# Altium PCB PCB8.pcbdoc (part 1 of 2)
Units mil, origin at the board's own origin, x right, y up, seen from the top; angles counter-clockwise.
Board outline 4659.3 x 3372.91 mil, 4 copper layers (Top Layer, Inner1, Inner2, Bottom Layer); 143 components, 120 nets, 588 pads, 154 vias.
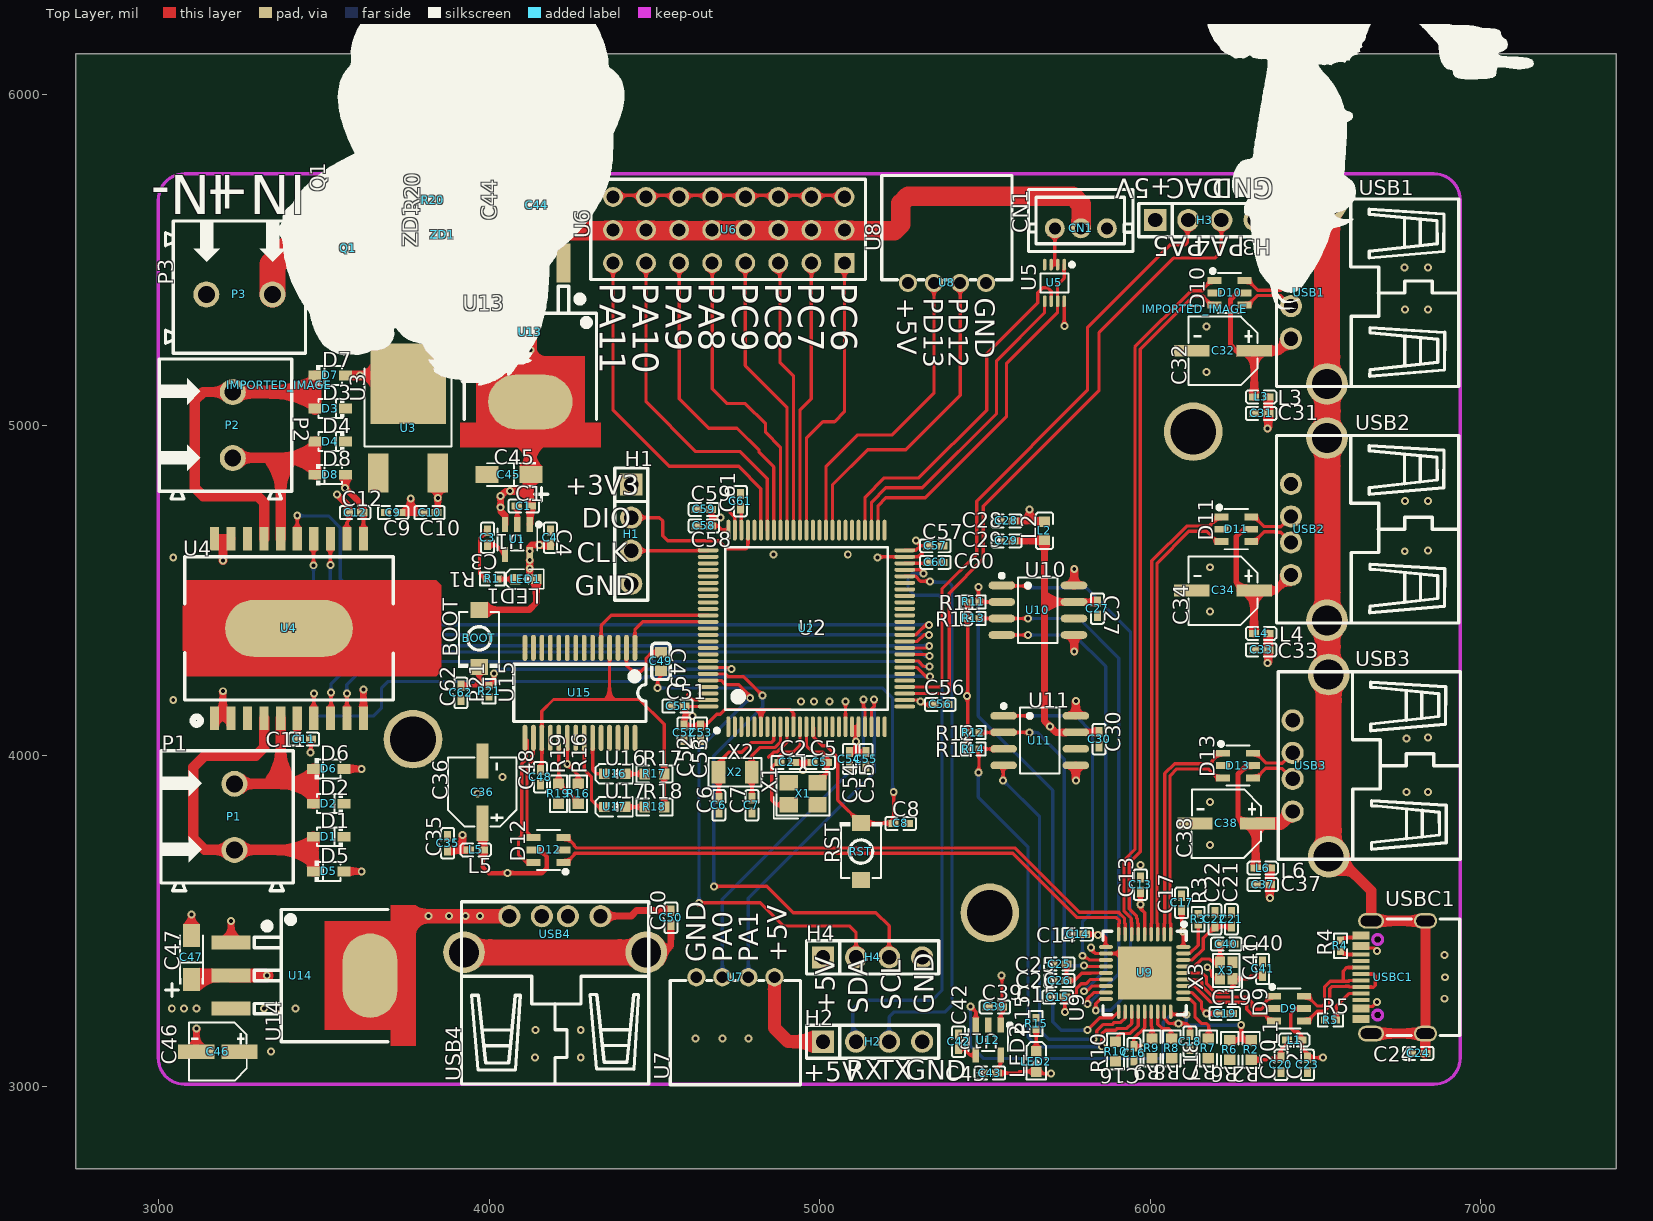
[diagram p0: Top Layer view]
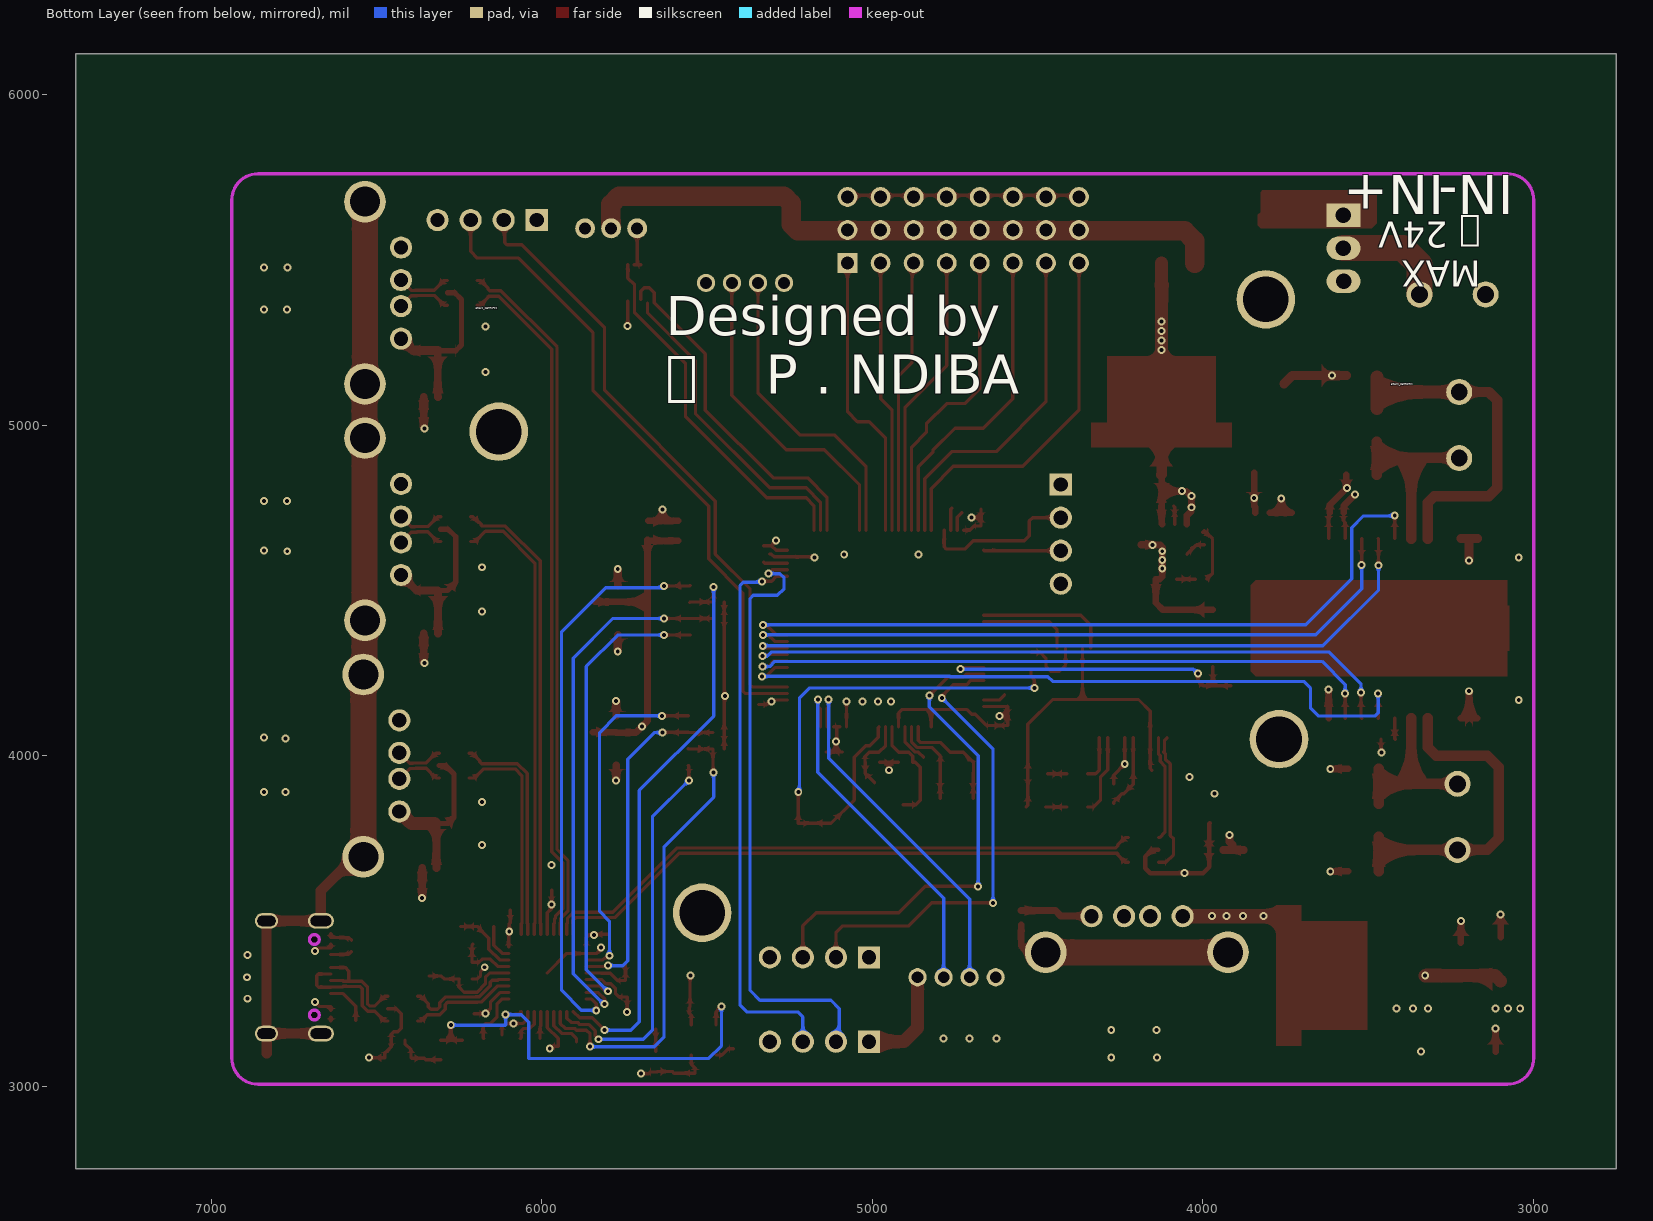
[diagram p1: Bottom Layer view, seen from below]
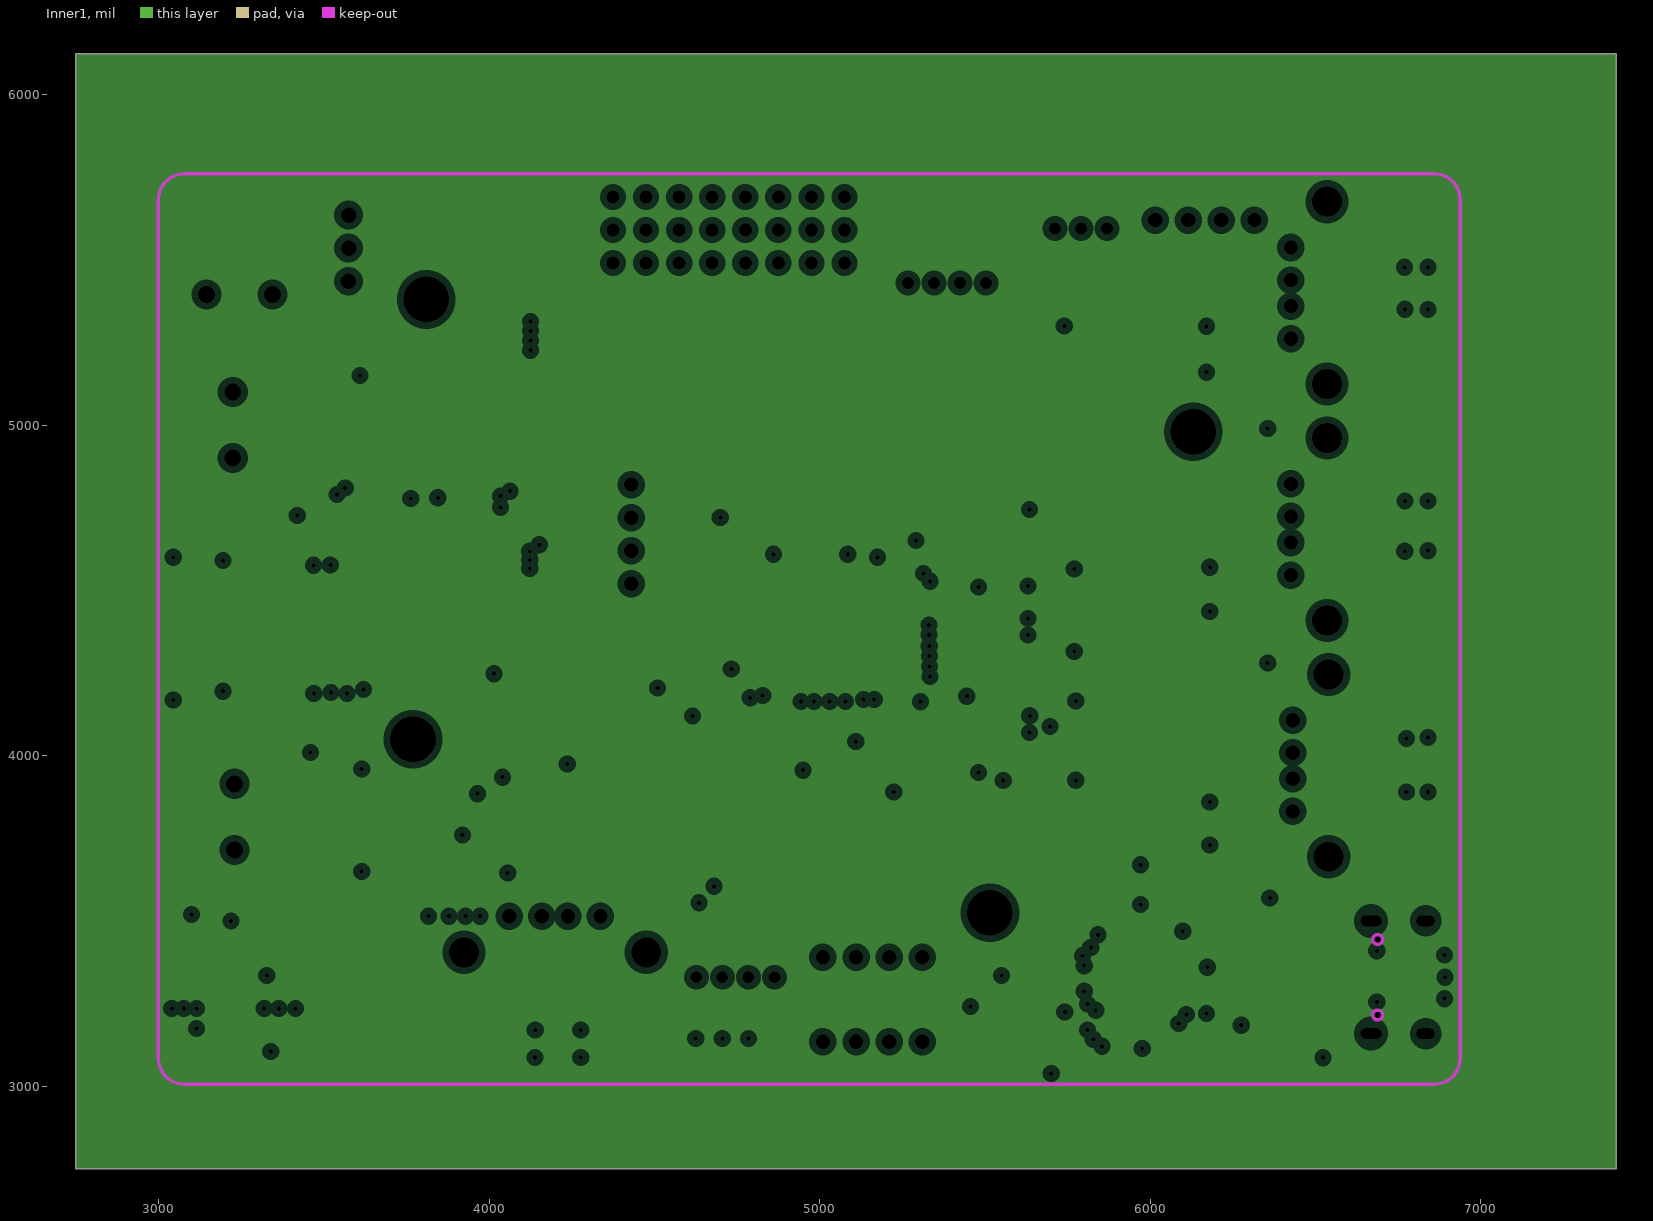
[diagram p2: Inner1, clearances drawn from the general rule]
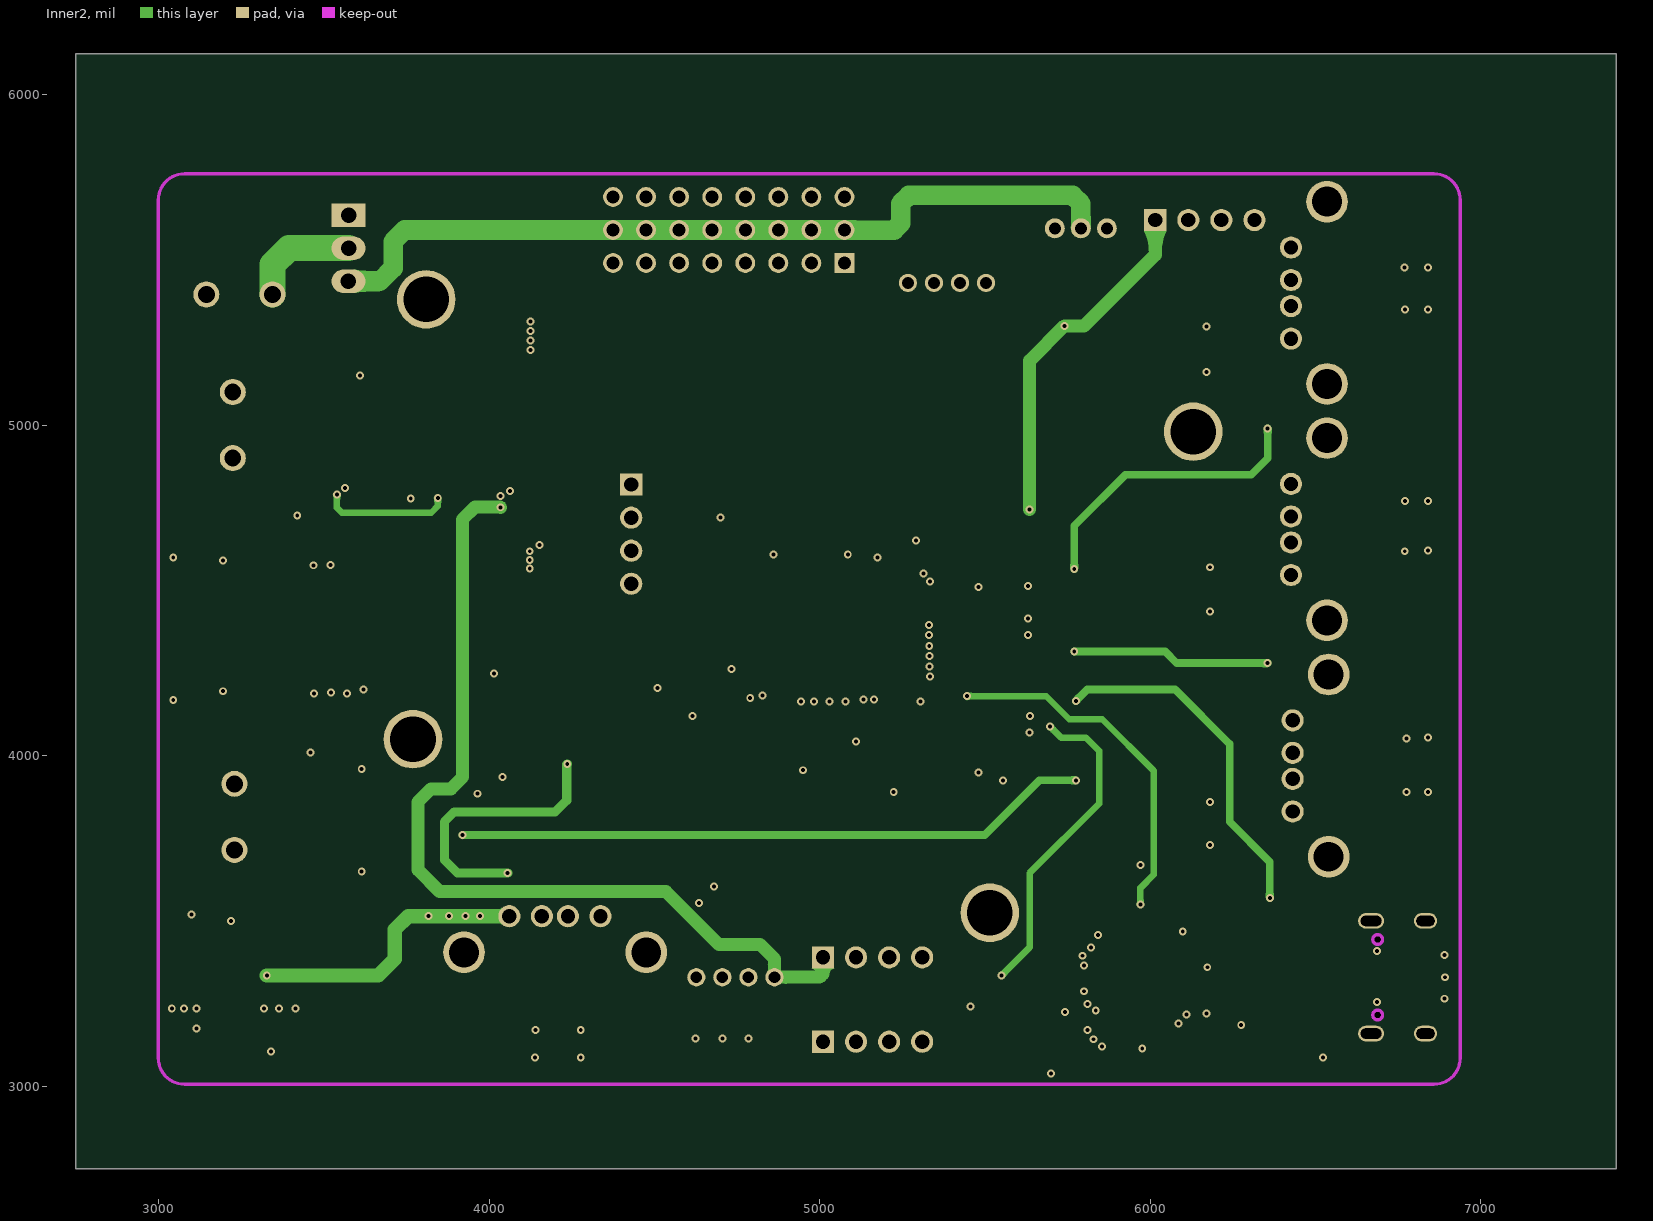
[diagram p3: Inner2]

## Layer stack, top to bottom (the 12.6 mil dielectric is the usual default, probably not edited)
Top Layer: signal copper (thickness not stored)
Dielectric: dielectric 12.6, FR-4, Dk 4.8
Inner1: plane copper (thickness not stored)
Dielectric: dielectric 12.6, FR-4, Dk 4.8
Inner2: signal copper (thickness not stored)
Dielectric: dielectric 12.6, FR-4, Dk 4.8
Bottom Layer: signal copper (thickness not stored)

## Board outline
7409.3,2750 2750,2750 2750,6122.91 7409.3,6122.91

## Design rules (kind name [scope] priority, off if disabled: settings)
BoardOutlineClearance copperThickness1oz [All] p0: genericclearance=10 ignorepadtopadclearanceinfootprint=FALSE except(0: Arc-SplitContinuation Track-SplitContinuation SMDPad-SplitContinuation THPad-SplitContinuation Via-SplitContinuation Fill-SplitContinuation Poly-SplitContinuation Region-SplitContinuation Text-SplitContinuation; 6: Track-CutoutEdge SMDPad-CutoutEdge THPad-CutoutEdge Via-CutoutEdge Region-CutoutEdge; 11.8: Track-OutlineEdge SMDPad-OutlineEdge THPad-OutlineEdge Via-OutlineEdge Fill-OutlineEdge Region-OutlineEdge Poly-OutlineEdge Text-OutlineEdge Fill-CutoutEdge)
BoardOutlineClearance copperThickness2oz [All] p0: genericclearance=10 ignorepadtopadclearanceinfootprint=FALSE except(0: Arc-SplitContinuation Track-SplitContinuation SMDPad-SplitContinuation THPad-SplitContinuation Via-SplitContinuation Fill-SplitContinuation Poly-SplitContinuation Region-SplitContinuation Text-SplitContinuation; 6: Track-CutoutEdge SMDPad-CutoutEdge THPad-CutoutEdge Via-CutoutEdge Region-CutoutEdge; 11.8: Track-OutlineEdge SMDPad-OutlineEdge THPad-OutlineEdge Via-OutlineEdge Fill-OutlineEdge Region-OutlineEdge Poly-OutlineEdge Text-OutlineEdge Fill-CutoutEdge)
Clearance copperThickness1oz [(InNet('OSC_IN') OR InNet('GND') OR InNet('OSC_OUT') OR InNet('OSC32_IN') OR InNet('NRST') OR InNet('+5V-D1') OR InNet('VCC') OR InNet('$4N1148') OR InNet('$3N2967') OR InNet('3V3_HUB') OR InNet('+5V_USB_FIL') OR InNet('AGND') OR InNet('$3N5997') OR InNet('$3N6212') OR InNet('XTALIN') OR InNet('XTALOUT') OR InNet('+5V_HOST_FIL') OR InNet('5V_HOST') OR InNet('$3N9069') OR InNet('+5V_USB_PORT2') OR InNet('$3N12252') OR InNet('+5V_USB_PORT3') OR InNet('$3N14705') OR InNet('+5V_USB_PORT4') OR InNet('+5V_USB_PORT1_FIL') OR InNet('+5V_USB_PORT1') OR InNet('+5V') OR InNet('$1N3755') OR InNet('+3V3') OR InNet('DUP_SERVO') OR InNet('OUT1') OR InNet('OUT2') OR InNet('OUT4') OR InNet('OUT3') OR InNet('USBDP_UP') OR InNet('USBDM_UP') OR InNet('C_DN') OR InNet('C_DP') OR InNet('USBDP_DN2') OR InNet('USBDM_DN2') OR InNet('$3N10765') OR InNet('$3N9020') OR InNet('USBDP_DN3') OR InNet('USBDM_DN3') OR InNet('$3N12261') OR InNet('$3N12248') OR InNet('USBDP_DN4') OR InNet('USBDM_DN4') OR InNet('$3N14709') OR InNet('$3N14704') OR InNet('USB1_DM') OR InNet('USB1_DP') OR InNet('VCCIO') OR InNet('$3N4638') OR InNet('$1N3758') OR InNet('$4N1145') OR InNet('$4N1153') OR InNet('$4N1154') OR InNet('$3N3794') OR InNet('$3N3790') OR InNet('$3N4557') OR InNet('$3N4535') OR InNet('$3N4529') OR InNet('$3N4524') OR InNet('VBUS_DET') OR InNet('$3N5818') OR InNet('USB_HUB_NOCS1') OR InNet('USB_HUB_NOCS2') OR InNet('PC9') OR InNet('PC8') OR InNet('PC7') OR InNet('PC6') OR InNet('ENC3_2') OR InNet('ENC3_1') OR InNet('ENB') OR InNet('ENA') OR InNet('ENC1_2') OR InNet('ENC1_1') OR InNet('OSC32_OUT') OR InNet('IN1') OR InNet('IN2') OR InNet('IN3') OR InNet('IN4') OR InNet('TX1') OR InNet('RX1') OR InNet('$4N1151') OR InNet('$4N1152') OR InNet('DUP_TX') OR InNet('DUP_RX') OR InNet('DUP_CTRL') OR InNet('USBDM_DN1') OR InNet('USBDP_DN1') OR InNet('USB_HUB_NOCS3') OR InNet('USB_HUB_PWR4') OR InNet('USB_HUB_NOCS4') OR InNet('USB_HUB_PWR3') OR InNet('USB_HUB_PWR2') OR InNet('USB_HUB_PWR1') OR InNet('$4N2277') OR InNet('+5V_PI') OR InNet('$4N3409') OR InNet('$4N3607') OR InNet('PA11') OR InNet('PA10') OR InNet('PA9') OR InNet('PA8') OR InNet('SWCLK') OR InNet('$1N6732') OR InNet('SWDIO') OR InNet('$1N6736') OR InNet('DEBUG_RX') OR InNet('DEBUG_TX') OR InNet('SDA') OR InNet('SCL') OR InNet('BOOT') OR InNet('MOSI') OR InNet('MISO') OR InNet('SCK') OR InNet('DAC2') OR InNet('DAC1'))] p1: gap=7 ignorepadtopadclearanceinfootprint=FALSE except(4: Track-Track; 6: Track-SMDPad SMDPad-SMDPad Track-THPad SMDPad-THPad THPad-THPad Track-Via SMDPad-Via THPad-Via Via-Via SMDPad-Fill THPad-Fill Via-Fill Fill-Fill Track-Region SMDPad-Region THPad-Region Via-Region Region-Region Track-Poly SMDPad-Poly THPad-Poly Via-Poly Fill-Poly Region-Poly Poly-Poly Track-Text SMDPad-Text THPad-Text Via-Text Fill-Text Region-Text Poly-Text Text-Text; 6.9: Track-Hole SMDPad-Hole THPad-Hole Via-Hole Fill-Hole Region-Hole Poly-Hole Text-Hole Sheet-Hole; 11.8: Track-Fill Fill-Region Track-Sheet SMDPad-Sheet THPad-Sheet Via-Sheet Fill-Sheet Region-Sheet Poly-Sheet Text-Sheet)
Clearance copperThickness2oz [All] p1: gap=7 ignorepadtopadclearanceinfootprint=FALSE except(6: Track-SMDPad SMDPad-SMDPad Track-THPad SMDPad-THPad THPad-THPad Track-Via SMDPad-Via THPad-Via Via-Via SMDPad-Fill THPad-Fill Via-Fill Fill-Fill Track-Region SMDPad-Region THPad-Region Via-Region Region-Region Track-Poly SMDPad-Poly THPad-Poly Via-Poly Fill-Poly Region-Poly Poly-Poly Track-Text SMDPad-Text THPad-Text Via-Text Fill-Text Region-Text Poly-Text Text-Text; 6.9: Track-Hole SMDPad-Hole THPad-Hole Via-Hole Fill-Hole Region-Hole Poly-Hole Text-Hole Sheet-Hole; 8: Track-Track; 11.8: Track-Fill Fill-Region Track-Sheet SMDPad-Sheet THPad-Sheet Via-Sheet Fill-Sheet Region-Sheet Poly-Sheet Text-Sheet)
DiffPairsRouting differentialPair [All] p1: maxuncoupledlength=10 minlimit=6 maxlimit=6 mostfreqgap=6 toplayer_minwidth=5 toplayer_prefwidth=10 toplayer_maxwidth=100 bottomlayer_minwidth=5 bottomlayer_prefwidth=10 bottomlayer_maxwidth=100 midlayer2_minwidth=5 midlayer2_prefwidth=10 midlayer2_maxwidth=100
PasteMaskExpansion pasteMaskExpansion [All] p1: expansion=0
PlaneConnect innerPlane [All] p1: planeconnectstyle=Relief reliefexpansion=20 reliefentries=4 reliefconductorwidth=10 reliefairgap=10
PolygonConnect copperRegion [All] p1: connectstyle=Relief reliefentries=4 reliefconductorwidth=10 polygonreliefangle="90 Angle" airgapwidth=10
RoutingVias viaSize [All] p1: viastyle="Through Hole" holewidth=12.0078 minholewidth=11.811 maxholewidth=248.0314 width=24.0158 minwidth=19.685 maxwidth=393.7008
SolderMaskExpansion solderMaskExpansion [All] p1: useseparateexpansions=TRUE expansion=2 expansionbottom=2
Width copperThickness1oz [All] p1: maxlimit=100 minlimit=5 preferedwidth=10
Width copperThickness2oz [All] p1: maxlimit=100 minlimit=8 preferedwidth=10

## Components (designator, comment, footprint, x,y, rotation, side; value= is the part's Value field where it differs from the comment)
BOOT "TS-1088-AR02016" SW-SMD_L3.9-W3.0-P4.45 3970,4354.8 r270 top
C1 "CL05A225MQ5NSNC" C0402 4105,4754.8 r180 top
C2 "TCC0402COG250K500AT" C0402 4900,3979.8 r180 top
C3 "CC0402KRX7R7BB104" C0402 3995.76,4659.01 r270 top
C4 "CL05A225MQ5NSNC" C0402 4185.76,4659.01 r270 top
C5 "TCC0402COG250K500AT" C0402 5000,3979.8 r0 top
C6 "TCC0402COG250K500AT" C0402 4695,3849.8 r90 top
C7 "TCC0402COG250K500AT" C0402 4795,3849.8 r90 top
C8 "CT41G-0402-2X1-16V-0.1μF-K(N)" C0402 5245,3794.8 r180 top
C9 "CL05A105KP5NNNC" C0402 3710,4734.8 r180 top
C10 "CT41G-0402-2X1-16V-0.1μF-K(N)" C0402 3820,4734.8 r0 top
C11 "GRM155R71C104KA88D" C0402 3440,4049.8 r180 top
C12 "GRM155R71C104KA88D" C0402 3595,4734.8 r180 top
C13 "CL05A225MQ5NSNC" C0402 5970,3609.8 r270 top
C14 "CC0402KRX7R7BB104" C0402 5780,3459.8 r180 top
C15 "CC0402KRX7R7BB104" C0402 5720,3269.8 r180 top
C16 "CC0402KRX7R7BB104" C0402 5950,3099.8 r270 top
C17 "CC0402KRX7R7BB104" C0402 6095,3554.8 r90 top
C18 "CC0402KRX7R7BB104" C0402 6120,3134.8 r270 top
C19 "CC0402KRX7R7BB104" C0402 6225,3219.8 r180 top
C20 "CL05A225MQ5NSNC" C0402 6395,3064.8 r90 top
C21 "CC0402KRX7R7BB104" C0402 6245,3504.8 r90 top
C22 "CC0402KRX7R9BB103" C0402 6195,3504.8 r90 top
C23 "CL05A225MQ5NSNC" C0402 6475,3064.8 r90 top
C24 "CC0402KRX7R9BB472" C0402 6810,3099.8 r180 top
C25 "CC0402KRX7R9BB103" C0402 5725,3369.8 r180 top
C26 "CC0402KRX7R7BB104" C0402 5725,3319.8 r180 top
C27 "CT41G-0402-2X1-16V-0.1μF-K(N)" C0402 5840,4444.8 r90 top
C28 "CL05A225KO5NQNC" C0402 5565,4709.8 r180 top
C29 "CL05A225KO5NQNC" C0402 5565,4649.8 r180 top
C30 "CT41G-0402-2X1-16V-0.1μF-K(N)" C0402 5845,4049.8 r90 top
C31 "CL05A225MQ5NSNC" C0402 6335,5034.8 r0 top
C32 "RVT1C101M0505" CAP-SMD_BD5.0-L5.3-W5.3-LS6.3-FD 6220,5224.8 r180 top
C33 "CL05A225MQ5NSNC" C0402 6335,4319.8 r0 top
C34 "RVT1C101M0505" CAP-SMD_BD5.0-L5.3-W5.3-LS6.3-FD 6220,4499.8 r180 top
C35 "CL05A225MQ5NSNC" C0402 3875,3734.8 r270 top
C36 "RVT1C101M0505" CAP-SMD_BD5.0-L5.3-W5.3-LS6.3-FD 3980,3889.8 r90 top
C37 "CL05A225MQ5NSNC" C0402 6340,3609.8 r0 top
C38 "RVT1C101M0505" CAP-SMD_BD5.0-L5.3-W5.3-LS6.3-FD 6230,3794.8 r180 top
C39 "CL05A225MQ5NSNC" C0402 5530,3239.8 r180 top
C40 "0402CG100J500NT" C0402 6230,3429.8 r0 top
C41 "0402CG100J500NT" C0402 6340,3354.8 r90 top
C42 "CC0402KRX7R7BB104" C0402 5420,3134.8 r270 top
C43 "CL05A225MQ5NSNC" C0402 5515,3039.8 r0 top
C44 "RST10UF16V013" CAP-SMD_BD4.0-L4.3-W4.3-FD 4145,5664.8 r0 top
C45 "TAJA106K016RNJ" CAP-SMD_L3.2-W1.6-RD-C7171 4060,4849.8 r180 top
C46 "RST10UF16V013" CAP-SMD_BD4.0-L4.3-W4.3-FD 3180,3104.8 r180 top
C47 "TAJA106K016RNJ" CAP-SMD_L3.2-W1.6-RD-C7171 3100,3389.8 r90 top
C48 "CC0402KRX7R7BB104" C0402 4155,3934.8 r90 top
C49 "CC0603KRX7R9BB104" C0603 4520,4284.8 r270 top
C50 "CC0402KRX7R9BB472" C0402 4550,3509.8 r270 top
C51 "GRM155R71A104KA01D" C0402 4570,4149.8 r180 top
C52 "GRM155R71A104KA01D" C0402 4590,4069.8 r270 top
C53 "GRM155R71A104KA01D" C0402 4640,4069.8 r270 top
C54 "GRM155R71A104KA01D" C0402 5090,3989.8 r270 top
C55 "GRM155R71A104KA01D" C0402 5140,3989.8 r270 top
C56 "GRM155R71A104KA01D" C0402 5365,4154.8 r0 top
C57 "GRM155R71A104KA01D" C0402 5350,4634.8 r0 top
C58 "GRM155R71A104KA01D" C0402 4650,4694.8 r180 top
C59 "CL05A475KP5NRNC" C0402 4650,4744.8 r180 top
C60 "GRM155R61A225KE95D" C0402 5350,4584.8 r180 top
C61 "GRM155R61A225KE95D" C0402 4760,4769.8 r90 top
C62 "CT41G-0402-2X1-16V-0.1μF-K(N)" C0402 3915,4189.8 r90 top
CN1 "WAFER-PH2.0-3PZZ" CONN-TH_PH2.0D-L-3P 5790,5594.8 r0 top
D1 "1N5819WS_C191023" SOD-323_L1.8-W1.3-LS2.5-RD 3515,3754.8 r180 top
D2 "1N5819WS_C191023" SOD-323_L1.8-W1.3-LS2.5-RD 3515,3854.8 r180 top
D3 "1N5819WS_C191023" SOD-323_L1.8-W1.3-LS2.5-RD 3520,5049.8 r180 top
D4 "1N5819WS_C191023" SOD-323_L1.8-W1.3-LS2.5-RD 3520,4949.8 r180 top
D5 "1N5819WS_C191023" SOD-323_L1.8-W1.3-LS2.5-RD 3515,3649.8 r0 top
D6 "1N5819WS_C191023" SOD-323_L1.8-W1.3-LS2.5-RD 3515,3959.8 r0 top
D7 "1N5819WS_C191023" SOD-323_L1.8-W1.3-LS2.5-RD 3520,5149.8 r0 top
D8 "1N5819WS_C191023" SOD-323_L1.8-W1.3-LS2.5-RD 3520,4849.8 r0 top
D9 "USBLC6-2SC6_C2827654" SOT-23-6_L2.9-W1.6-P0.95-LS2.8-BL 6420,3234.8 r270 top
D10 "USBLC6-2SC6_C2827654" SOT-23-6_L2.9-W1.6-P0.95-LS2.8-BL 6240,5399.8 r270 top
D11 "USBLC6-2SC6_C2827654" SOT-23-6_L2.9-W1.6-P0.95-LS2.8-BL 6260,4684.8 r270 top
D12 "USBLC6-2SC6_C2827654" SOT-23-6_L2.9-W1.6-P0.95-LS2.8-BL 4180,3714.8 r90 top
D13 "USBLC6-2SC6_C2827654" SOT-23-6_L2.9-W1.6-P0.95-LS2.8-BL 6265,3969.8 r270 top
H1 "PZ254V-11-04P" HDR-TH_4P-P2.54-V-M 4430,4669.8 r270 top
H2 "PZ254V-11-04P" HDR-TH_4P-P2.54-V-M 5160,3134.8 r0 top
H3 "PZ254V-11-04P" HDR-TH_4P-P2.54-V-M 6165,5619.8 r0 top
H4 "PZ254V-11-04P" HDR-TH_4P-P2.54-V-M 5160,3389.8 r0 top
IMPORTED_IMAGE "IMPORTED_IMAGE" IMPORTED_IMAGE 3366.03,5119.8 r0 top
IMPORTED_IMAGE "IMPORTED_IMAGE" IMPORTED_IMAGE 6134.81,5349.8 r0 top
L1 "BLM15PX121SN1D" L0402 6435,3139.8 r180 top
L2 "BLM18KG121TN1D" L0603 5680,4679.8 r270 top
L3 "BLM15PX121SN1D" L0402 6335,5084.8 r180 top
L4 "BLM15PX121SN1D" L0402 6335,4369.8 r180 top
L5 "BLM15PX121SN1D" L0402 3960,3714.8 r0 top
L6 "BLM15PX121SN1D" L0402 6340,3659.8 r180 top
LED1 "XL-1608SURC-06" LED0603-RD_RED 4110.76,4534.01 r0 top
LED2 "XL-1608SURC-06" LED0603-RD_RED 5655,3074.8 r270 top
P1 "WJ500V-5.08-2P" CONN-TH_2P-P5.00_WJ500V-5.08-2P 3230,3814.8 r90 top
P2 "WJ500V-5.08-2P" CONN-TH_2P-P5.00_WJ500V-5.08-2P 3225,4999.8 r90 top
P3 "WJ500V-5.08-2P" CONN-TH_2P-P5.00_WJ500V-5.08-2P 3245,5394.8 r0 top
Q1 "IRF9540NPBF" TO-220-3_L10.0-W4.5-P2.54-L 3575,5534.8 r270 top
R1 "0402WGF3300TCE" R0402 4010,4534.8 r0 top
R2 "RC0603FR-07100KL" R0603 6305,3109.8 r270 top
R3 "RC0402FR-0712KL" R0402 6145,3504.8 r90 top
R4 "RMC04025.1K1%N" R0402 6575,3424.8 r270 top
R5 "RMC04025.1K1%N" R0402 6545,3199.8 r180 top
R6 "RC0603FR-07100KL" R0603 6240,3109.8 r90 top
R7 "RC0603FR-07100KL" R0603 6175,3114.8 r90 top
R8 "RC0603FR-07100KL" R0603 6065,3114.8 r90 top
R9 "RC0603FR-07100KL" R0603 6005,3114.8 r90 top
R10 "RC0603FR-07100KL" R0603 5895,3104.8 r90 top
R11 "RC0402FR-0710KL" R0402 5465,4464.8 r180 top
R12 "RC0402FR-0710KL" R0402 5465,4069.8 r180 top
R13 "RC0402FR-0710KL" R0402 5465,4414.8 r0 top
R14 "RC0402FR-0710KL" R0402 5465,4019.8 r0 top
R15 "0402WGF3300TCE" R0402 5655,3189.8 r270 top
R16 "RC0603JR-074K7L" R0603 4270,3884.8 r90 top
R17 "RT0603BRE07250RL" R0603 4500,3944.8 r0 top
R18 "RT0603BRE07250RL" R0603 4500,3844.8 r0 top
R19 "FRC0603J103TS" R0603 4210,3884.8 r270 top
R20 "RC0402FR-0710KL" R0402 3830,5679.8 r180 top
R21 "RC0402FR-0710KL" R0402 4000,4194.8 r90 top
RST "TS-1088-AR02016" SW-SMD_L3.9-W3.0-P4.45 5125,3709.8 r90 top
U1 "SPX3819M5-L-3-3/TR" SOT-23-5_L3.0-W1.7-P0.95-LS2.8-BL 4085.76,4654.01 r180 top
U2 "STM32H723VGT6" LQFP-100_L14.0-W14.0-P0.50-LS16.0-BL 4960,4384.8 r0 top
U3 "78M05_C347278" TO-252-2_L6.6-W6.1-P4.57-LS9.9-BR-CW 3755,4989.8 r270 top
U4 "XL298P" HSOP-20_L15.9-W11.0-P1.27-LS14.2-BL-EP 3395,4384.8 r0 top
U5 "SN74LVC2G241DCUR" VSSOP-8_L2.3-W2.0-P0.50-LS3.1-BR 5710,5429.8 r90 top
U6 "HX PZ2.54-3x8P ZZ" HDR-TH_24P-P2.54-V-F-R3-C8-S2.54 4725,5589.8 r180 top
U7 "WAFER-PH2.0-4PWZ" CONN-TH_4P-P2.00_WAFER-HY2.0-4PWZ 4745,3329.8 r180 top
U8 "WAFER-PH2.0-4PWZ" CONN-TH_4P-P2.00_WAFER-HY2.0-4PWZ 5385,5429.8 r0 top
U9 "USB2514B-AEZC-TR" VQFN-36_L6.0-W6.0-P0.50-BL-EP 5982.86,3342.64 r180 top
U10 "MIC2026-1YM-TR" SOIC-8_L4.9-W3.9-P1.27-LS6.0-BL 5660,4439.8 r270 top
U11 "MIC2026-1YM-TR" SOIC-8_L4.9-W3.9-P1.27-LS6.0-BL 5665.63,4045.43 r270 top
U12 "SPX3819M5-L-3-3/TR" SOT-23-5_L3.0-W1.7-P0.95-LS2.8-BL 5510,3139.8 r180 top
U13 "LM1084ISX-5.0/NOPB" TO-263-3_L10.2-W8.6-P2.54-LS14.4-TL 4125,5279.8 r270 top
U14 "LM1084ISX-5.0/NOPB" TO-263-3_L10.2-W8.6-P2.54-LS14.4-TL 3430,3334.8 r0 top
U15 "FT232RL-REEL" SSOP-28_L10.2-W5.3-P0.65-LS7.8-BL 4275,4189.8 r180 top
U16 "NCD0603C4" LED0603-RD 4380,3944.8 r0 top
U17 "NCD0603C4" LED0603-RD 4380,3844.8 r0 top
USB1 "901-211A1021D10100" USB-A-TH_USB-M-1_C2346 6480,5399.8 r0 top
USB2 "901-211A1021D10100" USB-A-TH_USB-M-1_C2346 6480,4684.8 r0 top
USB3 "901-211A1021D10100" USB-A-TH_USB-M-1_C2346 6485,3969.8 r0 top
USB4 "901-211A1021D10100" USB-A-TH_USB-M-1_C2346 4200,3459.8 r270 top
USBC1 "TYPE-C-31-M-12" USB-C_SMD-TYPE-C-31-M-12 6735,3329.8 r90 top
X1 "X322525MOB4SI" CRYSTAL-SMD_4P-L3.2-W2.5-BL 4950,3884.8 r0 top
X2 "X321532768KGD2SI" OSC-SMD_L3.2-W1.5 4743.99,3949.69 r180 top
X3 "XL7EL89CKI-111YLC-24M" CRYSTAL-SMD_4P-L2.0-W1.6-BL-A 6230,3349.8 r90 top
ZD1 "BZX84C33LT1G" SOT-23-3_L2.9-W1.6-P1.90-LS2.8-BR 3860,5574.8 r180 top

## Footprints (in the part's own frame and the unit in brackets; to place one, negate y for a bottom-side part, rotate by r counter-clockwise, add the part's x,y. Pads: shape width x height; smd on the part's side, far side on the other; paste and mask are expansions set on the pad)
C0402 [mm]
  rect 0.79x0.54 smd: 1(-0.545,0) 2(0.545,0)
  silkscreen extent -1.17,-0.5 1.17,0.5
C0603 [mm]
  rect 0.8x0.9 smd: 1(-0.7,0) 2(0.7,0)
  silkscreen extent -1.41,-0.71 1.39,0.72
CAP-SMD_BD4.0-L4.3-W4.3-FD [mm]
  rect 2.8x1.1 smd: 1(-1.661,0) 2(1.661,0)
  silkscreen extent -2.22,-2.23 2.24,2.23
CAP-SMD_BD5.0-L5.3-W5.3-LS6.3-FD [mm]
  rect 2.7x0.91 smd: 1(-2.4,0) 2(2.4,0)
  silkscreen extent -2.66,-2.62 2.66,2.65
CAP-SMD_L3.2-W1.6-RD-C7171 [mil]
  rect 69.19x51.02 smd: 1(-66.39,0) 2(66.39,0)
  silkscreen extent -118,-37 66,79
CONN-TH_2P-P5.00_WJ500V-5.08-2P [mm]
  round 2 hole 1.3: 1(-2.54,0) 2(2.54,0)
  silkscreen extent -5.68,-4.52 5.08,5.64
CONN-TH_4P-P2.00_WAFER-HY2.0-4PWZ [mm]
  round 1.4 hole 0.9: 1(-3,0) 2(-1,0) 3(1,0) 4(3,0)
  silkscreen extent -5,0.25 5,8.25
CONN-TH_PH2.0D-L-3P [mil]
  round 60 hole 36: 1(-78.74,0) 2(0,0) 3(78.74,0)
  silkscreen extent -159,-70 158,118
CRYSTAL-SMD_4P-L2.0-W1.6-BL-A [mm]
  rect 0.875x0.775 smd: 1(-0.638,-0.488) 2(0.638,-0.488) 3(0.638,0.488) 4(-0.638,0.488)
  silkscreen extent -1.49,-1.2 1.27,1.02
CRYSTAL-SMD_4P-L3.2-W2.5-BL [mm]
  rect 1.4x1.2 smd: 1(-1.1,-0.85) 2(1.1,-0.85) 3(1.1,0.85) 4(-1.1,0.85)
  silkscreen extent -2.26,-1.91 2.03,1.68
HDR-TH_4P-P2.54-V-M [mm]
  rect 1.7x1.7 hole 1.1: 1(-3.81,0)
  round 1.7 hole 1.1: 2(-1.27,0) 3(1.27,0) 4(3.81,0)
  silkscreen extent -5.08,-1.27 5.08,1.27
HDR-TH_24P-P2.54-V-F-R3-C8-S2.54 [mil]
  rect 60x60 hole 39.37: 1(-350,100)
  round 60 hole 39.37: 2(-250,100) 3(-150,100) 4(-50,100) 5(50,100) 6(150,100) 7(250,100) 8(350,100) 9(-350,0) 10(-250,0) 11(-150,0) 12(-50,0) 13(50,0) 14(150,0) 15(250,0) 16(350,0) 17(-350,-100) 18(-250,-100) 19(-150,-100) 20(-50,-100) 21(50,-100) 22(150,-100) 23(250,-100) 24(350,-100)
  silkscreen extent -413,-154 417,150
HSOP-20_L15.9-W11.0-P1.27-LS14.2-BL-EP [mm]
  rect 0.7x1.8 smd: 1(-5.715,-6.9) 2(-4.445,-6.9) 3(-3.175,-6.9) 4(-1.905,-6.9) 5(-0.635,-6.9) 6(0.635,-6.9) 7(1.905,-6.9) 8(3.175,-6.9) 9(4.447,-6.9) 10(5.715,-6.9) 11(5.715,6.9) 12(4.445,6.9) 13(3.175,6.9) 14(1.905,6.9) 15(0.635,6.9) 16(-0.635,6.9) 17(-1.905,6.9) 18(-3.175,6.9) 19(-4.445,6.9) 20(-5.715,6.9)
  oval 9.814x4.379 smd: 21(0,0)
  Top Layer region: -6.18,1.726 -6.18,3.649 6.18,3.649 6.18,1.726 8.178,1.726 8.178,-1.726 6.18,-1.726 6.18,-3.649 -6.18,-3.649 -6.18,-1.726 -8.178,-1.726 -8.178,1.726
  silkscreen extent -8,-7.38 8,5.5
IMPORTED_IMAGE [mil]
  silkscreen extent 0,0 1043,1585
L0402 [mm]
  rect 0.79x0.54 smd: 1(-0.545,0) 2(0.545,0)
  silkscreen extent -1.17,-0.5 1.17,0.5
L0603 [mm]
  rect 0.8x0.864 smd: 1(-0.7,0) 2(0.7,0)
  silkscreen extent -1.42,-0.65 1.41,0.67
LED0603-RD [mm]
  rect 0.8x0.8 smd: 1(-0.799,0) 2(0.799,0)
  silkscreen extent -1.49,-0.75 1.39,0.76
LED0603-RD_RED [mm]
  rect 0.8x0.8 smd: 1(-0.8,-0.003) 2(0.8,0.003)
  silkscreen extent -1.49,-0.75 1.39,0.76
LQFP-100_L14.0-W14.0-P0.50-LS16.0-BL [mm]
  oval 0.3x1.6 smd: 1(-6,-7.55) 2(-5.5,-7.55) 3(-5,-7.55) 4(-4.5,-7.55) 5(-4,-7.55) 6(-3.5,-7.55) 7(-3,-7.55) 8(-2.5,-7.55) 9(-2,-7.55) 10(-1.5,-7.55) 11(-1,-7.55) 12(-0.5,-7.55) 13(0,-7.55) 14(0.5,-7.55) 15(1,-7.55) 16(1.5,-7.55) 17(2,-7.55) 18(2.5,-7.55) 19(3,-7.55) 20(3.5,-7.55) 21(4,-7.55) 22(4.5,-7.55) 23(5,-7.55) 24(5.5,-7.55) 25(6,-7.55) 51(6,7.55) 52(5.5,7.55) 53(5,7.55) 54(4.5,7.55) 55(4,7.55) 56(3.5,7.55) 57(3,7.55) 58(2.5,7.55) 59(2,7.55) 60(1.5,7.55) 61(1,7.55) 62(0.5,7.55) 63(0,7.55) 64(-0.5,7.55) 65(-1,7.55) 66(-1.5,7.55) 67(-2,7.55) 68(-2.5,7.55) 69(-3,7.55) 70(-3.5,7.55) 71(-4,7.55) 72(-4.5,7.55) 73(-5,7.55) 74(-5.5,7.55) 75(-6,7.55)
  oval 1.6x0.3 smd: 26(7.55,-6) 27(7.55,-5.5) 28(7.55,-5) 29(7.55,-4.5) 30(7.55,-4) 31(7.55,-3.5) 32(7.55,-3) 33(7.55,-2.5) 34(7.55,-2) 35(7.55,-1.5) 36(7.55,-1) 37(7.55,-0.5) 38(7.55,0) 39(7.55,0.5) 40(7.55,1) 41(7.55,1.5) 42(7.55,2) 43(7.55,2.5) 44(7.55,3) 45(7.55,3.5) 46(7.55,4) 47(7.55,4.5) 48(7.55,5) 49(7.55,5.5) 50(7.55,6) 76(-7.55,6) 77(-7.55,5.5) 78(-7.55,5) 79(-7.55,4.5) 80(-7.55,4) 81(-7.55,3.5) 82(-7.55,3) 83(-7.55,2.5) 84(-7.55,2) 85(-7.55,1.5) 86(-7.55,1) 87(-7.55,0.5) 88(-7.55,0) 89(-7.55,-0.5) 90(-7.55,-1) 91(-7.55,-1.5) 92(-7.55,-2) 93(-7.55,-2.5) 94(-7.55,-3) 95(-7.55,-3.5) 96(-7.55,-4) 97(-7.55,-4.5) 98(-7.55,-5) 99(-7.55,-5.5) 100(-7.55,-6)
  silkscreen extent -7.03,-8 6.25,6.25
OSC-SMD_L3.2-W1.5 [mm]
  rect 1.05x1.7 smd: 1(-1.275,0) 2(1.275,0)
  silkscreen extent -2.03,-1.08 2.03,1.08
R0402 [mm]
  rect 0.566x0.54 smd: 1(-0.433,0) 2(0.433,0)
  silkscreen extent -0.94,-0.5 0.94,0.5
R0603 [mil]
  rect 31.75x34.02 smd: 1(-29.66,0) 2(29.66,0)
  silkscreen extent -55,-26 55,26
SOD-323_L1.8-W1.3-LS2.5-RD [mm]
  rect 1x0.75 smd: 1(-1.173,0) 2(1.173,0)
  silkscreen extent -1.08,-0.8 0.9,0.8
SOIC-8_L4.9-W3.9-P1.27-LS6.0-BL [mm]
  oval 0.588x2.045 smd: 1(-1.905,-2.772) 2(-0.635,-2.772) 3(0.635,-2.772) 4(1.905,-2.772) 5(1.905,2.772) 6(0.635,2.772) 7(-0.635,2.772) 8(-1.905,2.772)
  silkscreen extent -2.8,-2.92 2.53,1.52
SOT-23-3_L2.9-W1.6-P1.90-LS2.8-BR [mm]
  rect 1.07x0.6 smd: 1(1.235,-0.95) 2(1.235,0.95) 3(-1.235,0)
  silkscreen extent -0.88,-1.54 0.88,1.54
SOT-23-5_L3.0-W1.7-P0.95-LS2.8-BL [mm]
  rect 0.49x1.157 smd: 1(-0.95,-1.154) 2(0,-1.154) 3(0.95,-1.154)
  rect 0.49x1.175 smd: 4(0.95,1.154) 5(-0.95,1.154)
  silkscreen extent -1.8,-1.29 1.53,0.85
SOT-23-6_L2.9-W1.6-P0.95-LS2.8-BL [mil]
  rect 20.95x42.2 smd: 1(-37.4,-45.24) 2(0,-45.24) 3(37.4,-45.24) 4(37.4,45.24) 5(0,45.24) 6(-37.4,45.24)
  silkscreen extent -72,-57 61,35
SSOP-28_L10.2-W5.3-P0.65-LS7.8-BL [mil]
  oval 14.33x79.35 smd: 1(-166.34,-136.03) 2(-140.75,-136.03) 3(-115.16,-136.03) 4(-89.57,-136.03) 5(-63.98,-136.03) 6(-38.39,-136.03) 7(-12.79,-136.03) 8(12.8,-136.03) 9(38.39,-136.03) 10(63.98,-136.03) 11(89.57,-136.03) 12(115.16,-136.03) 13(140.75,-136.03) 14(166.34,-136.03) 15(166.34,136.03) 16(140.75,136.03) 17(115.16,136.03) 18(89.57,136.03) 19(63.98,136.03) 20(38.39,136.03) 21(12.8,136.03) 22(-12.79,136.03) 23(-38.39,136.03) 24(-63.98,136.03) 25(-89.57,136.03) 26(-115.16,136.03) 27(-140.75,136.03) 28(-166.34,136.03)
  silkscreen extent -200,-87 200,87
SW-SMD_L3.9-W3.0-P4.45 [mm]
  rect 1.23x1.36 smd: 1(-2.185,0) 2(2.185,0)
  silkscreen extent -2.03,-1.62 2.25,1.62
TO-220-3_L10.0-W4.5-P2.54-L [mm]
  rect 1.8x2.6 hole 1.2: 1(-2.54,0.005)
  oval 1.8x2.6 hole 1.2: 2(0,0.005)
  oval 1.8x2.6 hole 1.2 copper offset 0,0: 3(2.54,-0.005)
  silkscreen extent -5.3,-2.73 5.3,3.09
TO-252-2_L6.6-W6.1-P4.57-LS9.9-BR-CW [mm]
  rect 3x1.6 smd: 1(3.424,-2.29) 3(3.424,2.29)
  rect 6.2x5.8 smd: 2(-3.424,0)
  silkscreen extent -4.58,-3.35 1.38,3.35
TO-263-3_L10.2-W8.6-P2.54-LS14.4-TL [mm]
  rect 3x1.07 smd: 1(-5.338,2.54) 2(-5.338,0) 3(-5.338,-2.54)
  oval 4.194x6.48 smd: 4(5.338,0)
  Top Layer region: 1.842,-4.16 1.842,4.16 6.922,4.16 6.922,5.4 8.832,5.4 8.832,-5.4 6.922,-5.4 6.922,-4.16
  silkscreen extent -3.55,-5.08 6.69,5.08
USB-A-TH_USB-M-1_C2346 [mm]
  round 3.2 hole 2.3: 0(1.386,-7) 0(1.386,7)
  round 1.7 hole 1.1: 1(-1.386,-3.52) 2(-1.386,-1.019) 3(-1.386,0.98) 4(-1.386,3.48)
  silkscreen extent -2.49,-7.2 11.51,7.2
USB-C_SMD-TYPE-C-31-M-12 [mm]
  oval 1.2x2 hole 0.8 slot 1.6 at 90 deg: 0(-4.325,1.706) 1(4.325,1.706)
  oval 1.2x1.8 hole 0.8 slot 1.4 at 90 deg: 2(4.325,-2.474) 3(-4.325,-2.474)
  rect 0.3x1.3 smd: A1(-3.35,2.474) A4(-2.55,2.474) A5(-1.25,2.474) A6(-0.25,2.474) A7(0.25,2.474) A8(1.25,2.474) A9(2.55,2.474) A12(3.35,2.474) B1(3.05,2.474) B4(2.25,2.474) B5(1.75,2.474) B6(0.75,2.474) B7(-0.75,2.474) B8(-1.75,2.474) B9(-2.25,2.474) B12(-3.05,2.474)
  Board Outline Layer circle w0.005: c-2.9,1.206 r0.375
  Board Outline Layer circle w0.005: c2.9,1.206 r0.375
  Board Outline Layer circle w0.254: c-2.9,1.206 r0.375
  Board Outline Layer circle w0.254: c2.9,1.206 r0.375
  Multi-Layer board cut-out: -2.9,0.831 -2.714,0.882 -2.578,1.019 -2.528,1.206 -2.578,1.392 -2.714,1.529 -2.9,1.581 -2.9,1.581 -3.086,1.529 -3.222,1.392 -3.272,1.206 -3.222,1.019 -3.086,0.882 -2.9,0.831
  Multi-Layer board cut-out: 2.9,0.831 3.086,0.882 3.222,1.019 3.272,1.206 3.222,1.392 3.086,1.529 2.9,1.581 2.9,1.581 2.714,1.529 2.578,1.392 2.528,1.206 2.578,1.019 2.714,0.882 2.9,0.831
  silkscreen extent -4.47,-5.09 4.47,0.49
VQFN-36_L6.0-W6.0-P0.50-BL-EP [mm]
  oval 0.28x1.1 smd: 1(-2,-2.972) 2(-1.5,-2.972) 3(-1,-2.972) 4(-0.5,-2.972) 5(0,-2.972) 6(0.5,-2.972) 7(1,-2.972) 8(1.5,-2.972) 9(2,-2.972) 19(2,2.972) 20(1.5,2.972) 21(1,2.972) 22(0.5,2.972) 23(0,2.972) 24(-0.5,2.972) 25(-1,2.972) 26(-1.5,2.972) 27(-2,2.972)
  oval 1.1x0.28 smd: 10(2.972,-2) 11(2.972,-1.5) 12(2.972,-1) 13(2.972,-0.5) 14(2.972,0) 15(2.972,0.5) 16(2.972,1) 17(2.972,1.5) 18(2.972,2) 28(-2.972,2) 29(-2.972,1.5) 30(-2.972,1) 31(-2.972,0.5) 32(-2.972,0) 33(-2.972,-0.5) 34(-2.972,-1) 35(-2.972,-1.5) 36(-2.972,-2)
  rect 4.1x4.1 smd: 37(0,0)
  silkscreen extent -3.2,-3.9 3.2,3.2
VSSOP-8_L2.3-W2.0-P0.50-LS3.1-BR [mm]
  oval 0.905x0.28 smd: 1(1.403,-0.75) 2(1.403,-0.25) 3(1.403,0.25) 4(1.403,0.75) 5(-1.403,0.75) 6(-1.403,0.25) 7(-1.403,-0.25) 8(-1.403,-0.75)
  silkscreen extent -0.72,-1.49 1.55,1.08

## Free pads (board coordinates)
  round 177.17 hole 137.8: 1(5515,3524.8) 1(6130,4979.8) 2(3770,4049.8) 2(3810,5379.8)

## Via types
v1: diameter 24.02, hole 12.01, Top Layer to Bottom Layer, 154 vias

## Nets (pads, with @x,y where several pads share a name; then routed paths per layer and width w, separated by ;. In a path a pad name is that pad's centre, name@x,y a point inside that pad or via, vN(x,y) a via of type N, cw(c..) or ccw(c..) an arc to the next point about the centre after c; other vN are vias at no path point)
3V3_HUB: C13.2 C14.1 C15.1 C16.1 C17.1 C18.1 C19.2 C43.2 LED2.2 R11.2 R12.2 R13.1 R14.1 U9.5 U9.10 U9.15 U9.23 U9.26 U9.29 U9.36 U12.5 | length 2723.1
  Top Layer w10: R14.1@5447.96,4019.8 R12.2@5447.96,4069.8 R13.1@5447.96,4414.8 R11.2@5447.96,4464.8 ; U12.5@5547.4,3094.38 5547.4,3067.2 5536.46,3056.26 C43.2@5536.46,3039.8 5600,3039.8 5605,3044.8 5648.66,3044.8 5650.14,3043.33 5671.48,3043.33 5676.48,3038.33 v1(5700.14,3038.33) ; v1(5741.46,3224.8) C15.1@5741.46,3269.8 5765,3269.8 5777.01,3281.81 5777.01,3296.97 5790.48,3310.44 5805.63,3310.44 5818.16,3322.96 U9.15@5865.86,3322.96 ; C14.1@5801.46,3459.8 5840,3459.8 v1(5841.61,3458.19) 5856.61,3458.19 5865,3449.8 5865,3422.24 U9.10@5865.86,3421.38 ; C13.2@5970,3593.34 v1(5970,3549.41) 5970,3537.66 5982.86,3524.8 U9.5@5982.86,3459.64 ; v1(5975.67,3114.14) 5968.54,3121.26 C16.1@5950,3121.26 5950,3144.8 5982.86,3177.66 U9.23@5982.86,3225.64 ; U9.26@6041.91,3225.64 6041.91,3205.86 6057.96,3189.8 6110,3189.8 6120,3179.8 C18.1@6120,3156.26 ; C17.1@6095,3533.34 6095,3494.8 6098.17,3491.63 v1(6098.17,3468.62) 6099.86,3466.93 U9.36@6099.86,3421.38 ; U9.29@6099.86,3283.59 6126.21,3283.59 6155,3254.8 6155,3234.8 v1(6170,3219.8) C19.2@6203.54,3219.8
  Inner2 w19.68: v1(5445,4179.8) 5685,4179.8 5755,4109.8 5855,4109.8 6010,3954.8 6010,3639.8 5970,3599.8 v1(5970,3549.41)
  other v1: 6085.77,3189.8
5V_HOST: C23.2 D9.5 L1.1 USBC1.A4 USBC1.A9 USBC1.B4 USBC1.B9 | length 384.2
  Top Layer w10: D9.5@6465.24,3234.8 6440,3234.8 6425,3219.8 6425,3174.8 6435,3164.8 6447.93,3164.8 6455,3157.73 6455,3141.26 L1.1@6456.46,3139.8 6455,3138.34 6455,3119.8 6475,3099.8 C23.2@6475,3086.26 6521.74,3086.26 v1(6521.96,3086.49) ; USBC1.A4@6637.59,3229.41 USBC1.B9@6637.59,3241.22 6671.42,3241.22 v1(6685,3254.8) ; USBC1.A9@6637.59,3430.2 USBC1.B4@6637.59,3418.38 6676.42,3418.38 v1(6685,3409.8)
$1N3755: C3.2 U1.4 | length 64.6
  Top Layer w10: C3.2@3995.76,4637.55 4019.4,4637.55 U1.4@4048.36,4608.59
$1N3758: LED1.1 R1.2 | length 56.3
  Top Layer w10: R1.2@4022.94,4533.88 LED1.1@4079.28,4533.88
$1N6732: C61.1 U2.73 | length 67.6
  Top Layer w10: C61.1@4760,4748.34 4763.15,4745.19 U2.73@4763.15,4682.04
$1N6736: C60.2 U2.48 | length 72.6
  Top Layer w10: U2.48@5257.24,4581.65 5325.39,4581.65 C60.2@5328.54,4584.8
$3N2967: C42.2 U12.4 | length 60.5
  Top Layer w10: C42.2@5420,3113.34 5436.46,3113.34 5455.42,3094.38 U12.4@5472.6,3094.38
$3N3790: R4.2 USBC1.B5 | length 66.3
  Top Layer w10: R4.2@6575,3407.76 6584.06,3398.7 USBC1.B5@6637.59,3398.7
$3N3794: R5.1 USBC1.A5 | length 133.6
  Top Layer w10: R5.1@6562.04,3199.8 6562.04,3241.84 6600.79,3280.59 USBC1.A5@6637.59,3280.59
$3N4524: R10.2 U9.22 | length 137
  Top Layer w10: R10.2@5895,3134.46 5895,3144.8 5910,3159.8 5940,3159.8 5963.17,3182.97 U9.22@5963.17,3225.64
$3N4529: R9.2 U9.24 | length 82.2
  Top Layer w10: U9.24@6002.54,3225.64 6002.54,3182.27 6005,3179.8 R9.2@6005,3144.46
$3N4535: R8.2 U9.25 | length 110.4
  Top Layer w10: U9.25@6022.23,3225.64 6022.23,3187.99 6035.41,3174.8 6055,3174.8 6062.07,3167.73 6062.07,3147.39 R8.2@6065,3144.46
$3N4557: R7.2 U9.28 | length 173.4
  Top Layer w10: U9.28@6099.86,3263.9 6120.9,3263.9 6135,3249.8 6135,3209.8 6155,3189.8 6170,3189.8 6177.07,3182.73 6177.07,3146.54 R7.2@6175,3144.46
$3N4638: LED2.1 R15.2 | length 66.5
  Top Layer w10: LED2.1@5654.87,3106.29 5655,3106.42 R15.2@5655,3172.76
$3N5818: R3.1 U9.35 | length 111.5
  Top Layer w9.92: U9.35@6099.86,3401.7 6119.86,3401.7 6145,3426.85 R3.1@6145,3482.76
$3N5997: C21.1 C22.1 U9.34 | length 206.8
  Top Layer w10: U9.34@6099.86,3382.01 6127.21,3382.01 6160,3414.8 6160,3448.34 C22.1@6195,3483.34 C21.1@6245,3483.34
$3N6212: C25.1 C26.1 U9.14 | length 180.1
  Top Layer w10: C25.1@5746.46,3369.8 5746.46,3343.53 ; 5747.35,3342.64 5746.46,3343.53 ; U9.14@5865.86,3342.64 5820.36,3342.64 5819.52,3341.81 5792.01,3341.81 5770,3319.8 C26.1@5746.46,3319.8 5746.46,3343.53
$3N9020: D13.6 USB3.3 | length 145.7
  Top Layer w10: D13.6@6310.24,4007.2 6319.95,4007.2 6349.35,3977.8 6388.35,3977.8 6389.1,3977.05 6399.1,3977.05 USB3.3@6430.45,4008.4
$3N9069: C38.1 D13.5 L6.2 USB3.1 | length 507.4
  Top Layer w15.75: D13.5@6310.24,3969.8 6290.71,3969.8 6265,3944.09 6265,3813.11 6283.31,3794.8 C38.1@6319.49,3794.8
  Top Layer w23.62: L6.2@6318.54,3659.8 6318.54,3788.85 C38.1@6324.49,3794.8
  Top Layer w39.37: C38.1@6324.49,3794.8 6394.05,3794.8 USB3.1@6430.45,3831.2
$3N10765: D13.4 USB3.2 | length 145.7
  Top Layer w10: D13.4@6310.24,3932.4 6319.95,3932.4 6349.35,3961.8 6381.72,3961.8 6382.47,3961.05 6399.1,3961.05 USB3.2@6430.45,3929.7
$3N12248: D11.6 USB2.3 | length 145.7
  Top Layer w10: D11.6@6305.24,4722.2 6314.95,4722.2 6344.35,4692.8 6383.35,4692.8 6384.1,4692.05 6394.1,4692.05 USB2.3@6425.45,4723.4
$3N12252: C34.1 D11.5 L4.2 USB2.1 | length 517.2
  Top Layer w15.75: D11.5@6305.24,4684.8 6282.97,4684.8 6260,4661.84 6260,4524.8 6285,4499.8 C34.1@6314.49,4499.8
  Top Layer w23.62: L4.2@6313.54,4369.8 6313.54,4498.85 C34.1@6314.49,4499.8 6379.05,4499.8 USB2.1@6425.45,4546.2
$3N12261: D11.4 USB2.2 | length 145.7
  Top Layer w10: D11.4@6305.24,4647.4 6314.95,4647.4 6344.35,4676.8 6376.72,4676.8 6377.47,4676.05 6394.1,4676.05 USB2.2@6425.45,4644.7
$3N14704: D10.6 USB1.3 | length 165.7
  Top Layer w10: D10.6@6285.24,5437.2 6294.95,5437.2 6324.35,5407.8 6383.35,5407.8 6384.1,5407.05 6394.1,5407.05 USB1.3@6425.45,5438.4
$3N14705: C32.1 D10.5 L3.2 USB1.1 | length 528.9
  Top Layer w15.75: D10.5@6285.24,5399.8 6262.97,5399.8 6242.5,5379.34 6242.5,5242.3 6260,5224.8 C32.1@6314.49,5224.8
  Top Layer w23.62: L3.2@6313.54,5084.8 L3.2@6314.49,5085.75 ; L3.2@6314.49,5090.75 C32.1@6314.49,5224.8
  Top Layer w27.56: C32.1@6314.49,5224.8 6389.05,5224.8 USB1.1@6425.45,5261.2
$3N14709: D10.4 USB1.2 | length 165.7
  Top Layer w10: D10.4@6285.24,5362.4 6294.95,5362.4 6324.35,5391.8 6376.72,5391.8 6377.47,5391.05 6394.1,5391.05 USB1.2@6425.45,5359.7
$4N1145: R16.1 R19.1 U15.19 | length 227
  Top Layer w10: U15.19@4211.02,4053.77 4211.02,3915.48 R19.1@4210,3914.46 4239.66,3884.8 4245,3884.8 4270,3859.8 R16.1@4270,3855.14
$4N1148: C49.1 U15.2 | length 202.5
  Top Layer w10: U15.2@4415.75,4325.83 4415.75,4274.05 4435,4254.8 4460,4254.8 4475,4269.8 4475,4294.8 4492.56,4312.36 C49.1@4520,4312.36
$4N1151: U15.23 U16.1 | length 137.3
  Top Layer w10: U15.23@4313.39,4053.77 4313.39,3956.41 4325,3944.8 U16.1@4348.52,3944.8
$4N1152: U15.22 U17.1 | length 245
  Top Layer w10: U15.22@4287.79,4053.77 4287.79,3957.01 4310,3934.8 4310,3864.8 4330.01,3844.8 U17.1@4348.52,3844.8
$4N1153: R17.1 U16.2 | length 58.9
  Top Layer w10: U16.2@4411.48,3944.81 R17.1@4470.34,3944.8
$4N1154: R18.1 U17.2 | length 63.9
  Top Layer w10: U17.2@4411.48,3844.81 R18.1@4475.34,3844.81
$4N2277: Q1.1 R20.2 ZD1.1
$4N3409: C50.2 USB4.0 | length 697.2
  Top Layer w19.68: USB4.0@4475.6,3405.25 4530.45,3405.25 4550,3424.8 C50.2@4550,3488.34
  Top Layer w78.74: USB4.0@3924.4,3405.25 USB4.0@4475.6,3405.25
$4N3607: P3.2 Q1.2 | length 681.8
  Top Layer w78.74: P3.2@3345,5394.8 3345,5484.8 3395,5534.8 Q1.2@3575.2,5534.81
  Inner2 w78.74: P3.2@3345,5394.8 3345,5484.8 3395,5534.8 Q1.2@3575.2,5534.81
+3V3: BOOT.1 C4.2 C51.1 C52.1 C53.1 C54.1 C55.1 C56.1 C57.1 C58.1 C59.1 H1.1 LED1.2 U1.5 U2.6 U2.11 U2.20 U2.21 U2.27 U2.50 U2.75 U2.100 | length 1509.1
  Top Layer w10: v1(4615,4119.8) 4611.57,4123.24 4591.46,4123.24 ; U2.100@4662.76,4148.58 4592.68,4148.58 C51.1@4591.46,4149.8 4591.46,4123.24 ; C59.1@4671.46,4744.8 4671.46,4720.24 C58.1@4671.46,4694.8 4692.24,4694.8 4705,4682.04 U2.75@4723.78,4682.04 ; 4671.52,4720.17 v1(4699.47,4720.17) ; U2.6@4822.2,4087.56 4822.2,4139.8 ; U2.11@4920.63,4087.56 4920.63,4129.17 4910,4139.8 4822.2,4139.8 ; C54.1@5090,4011.26 5110.08,4011.26 ; U2.20@5097.8,4087.56 5107.4,4087.56 ; U2.21@5117.48,4087.56 5107.4,4087.56 ; C55.1@5140,4011.26 5110.08,4011.26 ; U2.27@5257.24,4168.26 5300.26,4168.26 v1(5305.26,4163.26) 5311.54,4163.26 5320,4154.8 C56.1@5343.54,4154.8 ; U2.50@5257.24,4621.02 5291.22,4621.02 5305,4634.8 ; v1(5291.22,4651.02) 5291.22,4648.58 5305,4634.8 ; C57.1@5328.54,4634.8 5305,4634.8 ; 4591.46,4123.24 4590,4121.78 C52.1@4590,4091.26 C53.1@4640,4091.26 4655,4091.26 4688.54,4124.8 4700,4124.8 4715,4139.8 4822.2,4139.8 ; 5107.4,4087.56 5107.4,4044.61 v1(5109.41,4042.6) 5110.08,4041.94 5110.08,4011.26
  Top Layer w19.68: BOOT.1@3970,4440.82 4121.02,4440.82 4142.5,4462.3 4142.5,4533.89 LED1.2@4142.24,4534.15 4130.66,4534.15 4123.16,4541.64 v1(4123.16,4565.95) v1(4123.16,4591.95) U1.5@4123.16,4608.59 4123.16,4632.01 4128.7,4637.55 v1(4152.12,4637.55)
  Top Layer w23.62: v1(4152.12,4637.55) C4.2@4185.76,4637.55
  other v1: 4123.16,4618.13
+5V: C1.1 C28.1 C45.1 H2.1 H3.1 H4.1 L2.1 U1.1 U1.3 U5.8 U7.1 U8.1 U13.2 U13.4 | length 5304.3
  Top Layer w10: U5.8@5739.53,5374.58 5739.53,5310.27 5740,5309.8 v1(5740,5299.8)
  Top Layer w19.68: U1.3@4048.36,4699.43 4048.36,4726.44 4035,4739.8 v1(4035,4751.2) v1(4035,4784.8) 4050,4799.8 v1(4063.12,4799.8) 4125,4799.8 ; U1.1@4123.16,4699.43 4125,4701.27 C1.1@4125,4753.34 ; C45.1@4126.39,4849.8 4125,4848.41 4125,4799.8 ; C1.1@4126.46,4754.8 4125,4756.26 4125,4799.8 ; C28.1@5586.46,4709.8 5635.18,4709.8 ; v1(5635,4744.8) 5635,4709.99 5635.18,4709.8 ; L2.1@5677.56,4709.8 5635.18,4709.8
  Top Layer w31.5: U13.4@4124.99,5069.66 4124.99,4851.2 C45.1@4126.39,4849.8
  Top Layer w39.37: U13.2@4124.82,5489.94 4124.82,5312.87 v1(4125,5312.68) v1(4125,5284.82) v1(4125,5255.3) v1(4125,5226.35) U13.4@4125,5059.67 ; U7.1@4863.11,3329.81 4863.11,3176.69 4905,3134.8 H2.1@5010,3134.8
  Inner2 w39.37: v1(4035,4751.2) 4033.56,4752.64 3957.84,4752.64 3920,4714.8 3920,3934.8 3885,3899.8 3824.37,3899.8 3785,3860.43 3785,3654.8 3851,3588.8 4535.21,3588.8 4695.21,3428.8 4820.21,3428.8 4863.32,3385.69 4863.32,3330.01 U7.1@4863.11,3329.81 5000,3329.8 5010,3339.8 H4.1@5010,3389.8 ; v1(5635,4744.8) 5635,5194.8 v1(5740,5299.8) 5800,5299.8 6015,5514.8 H3.1@6015,5619.8
+5V-D1: C10.2 C12.2 U3.3 U4.12 | length 656.1
  Top Layer w10: U4.12@3570,4656.45 3570,4704.8 3575,4709.8 3575,4733.34 C12.2@3573.54,4734.8
  Top Layer w19.68: v1(3540,4789.8) 3573.54,4756.26 C12.2@3573.54,4734.8 ; C10.2@3841.46,4734.8 3841.46,4751.26 3845,4754.8 v1(3845,4779.8) 3845,4854.84 U3.3@3845.16,4855
  Inner2 w19.68: v1(3540,4789.8) 3540,4749.8 3555,4734.8 3825,4734.8 3845,4754.8 v1(3845,4779.8)
+5V_HOST_FIL: C20.2 L1.2 R2.2 | length 153.8
  Top Layer w10: R2.2@6305,3080.14 6350.34,3080.14 6355,3084.8 6393.54,3084.8 C20.2@6395,3086.26 6395,3109.8 6413.54,3128.34 L1.2@6413.54,3139.8
+5V_PI: C47.1 U14.2 U14.4 USB4.1 | length 1643.2
  Top Layer w39.37: C47.1@3100,3318.41 3116.39,3334.8 U14.2@3219.86,3334.8
  Top Layer w41.34: U14.2@3219.86,3334.8 v1(3327.84,3334.8)
  Top Layer w43.31: U14.4@3640.14,3334.79 3669.99,3334.79 3710,3374.8 3710,3464.8 3759.55,3514.35 v1(3816.59,3514.35) v1(3879.27,3514.35) v1(3929.25,3514.35) v1(3972.45,3514.35) USB4.1@4061.4,3514.35
  Inner2 w43.31: v1(3327.84,3334.8) 3665,3334.8 3715,3384.8 3715,3474.01 3755.34,3514.35 v1(3816.59,3514.35) v1(3879.27,3514.35) v1(3929.25,3514.35) v1(3972.45,3514.35) USB4.1@4061.4,3514.35
+5V_USB_FIL: C27.2 C29.1 C30.2 C39.1 L2.2 U10.7 U11.7 U12.1 | length 2117.5
  Top Layer w10: U12.1@5547.4,3185.22 5547.4,3214.8 5553.7,3221.1 5553.7,3237.56 C39.1@5551.46,3239.8 5551.46,3333.34 v1(5550,3334.8)
  Top Layer w19.68: C29.1@5586.46,4649.8 L2.2@5680,4649.8 ; L2.2@5680,4652.25 L2.2@5680,4649.8 ; U10.7@5769.1,4464.85 5680,4464.85 ; U10.7@5769.15,4464.8 5840,4464.8 C27.2@5840,4466.26 ; C30.2@5845,4071.26 5844.17,4070.43 U11.7@5774.78,4070.43 5774.15,4069.8 5715,4069.8 v1(5696.4,4088.41) 5680,4104.8 5680,4464.85 ; 5680,4464.85 L2.2@5680,4649.8
  Inner2 w19.68: v1(5550,3334.8) 5635,3419.8 5635,3644.8 5845,3854.8 5845,4014.8 5805,4054.8 5730,4054.8 v1(5696.4,4088.41)
+5V_USB_PORT1: C37.2 L6.1 U11.8 | length 1198.1
  Top Layer w23.62: U11.8@5774.78,4120.43 v1(5774.78,4165.43) ; v1(6361.46,3569.8) C37.2@6361.46,3609.8 L6.1@6361.46,3659.8
  Inner2 w23.62: v1(5774.78,4165.43) 5809.15,4199.8 6075,4199.8 6240,4034.8 6240,3799.8 6361.46,3678.34 v1(6361.46,3569.8)
+5V_USB_PORT1_FIL: C36.1 D12.5 L5.2 R16.2 U15.20 | length 1407.3
  Top Layer w10: U15.20@4236.61,4053.77 v1(4236.61,3974.8) 4270,3941.41 R16.2@4270,3914.46
  Top Layer w13.78: C36.1@3980,3795.31 3981.46,3793.85 L5.2@3981.46,3714.8 3981.46,3663.34 4000,3644.8 v1(4056.5,3644.8) 4160,3644.8 4175,3659.8 4175,3694.8 4155,3714.8 D12.5@4134.76,3714.8
  Inner2 w27.56: v1(4056.5,3644.8) 3905,3644.8 3865,3684.8 3865,3799.8 3895,3829.8 4200,3829.8 4235,3864.8 4235,3973.19 v1(4236.61,3974.8)
+5V_USB_PORT2: C33.2 L4.1 U10.5 | length 740.5
  Top Layer w23.62: U10.5@5769.15,4364.8 5770,4363.95 v1(5770,4314.8) ; v1(6355,4279.8) 6356.46,4281.26 C33.2@6356.46,4319.8 L4.1@6356.46,4369.8
  Inner2 w23.62: v1(5770,4314.8) 6045,4314.8 6080,4279.8 v1(6355,4279.8)
+5V_USB_PORT3: C31.2 L3.1 U10.8 | length 1035.9
  Top Layer w23.62: U10.8@5769.15,4514.8 5770,4515.65 v1(5770,4564.8) ; v1(6355,4989.8) 6356.46,4991.26 C31.2@6356.46,5034.8 L3.1@6356.46,5084.8
  Inner2 w23.62: v1(5770,4564.8) 5770,4694.8 5925,4849.8 6305,4849.8 6355,4899.8 v1(6355,4989.8)
+5V_USB_PORT4: C35.2 L5.1 U11.5 | length 2079.9
  Top Layer w23.62: C35.2@3876.59,3714.8 3908.87,3714.8 ; v1(3920,3759.8) 3920,3739.8 3910,3729.8 3910,3715.93 3908.87,3714.8 ; L5.1@3938.54,3714.8 3908.87,3714.8 ; v1(5774.78,3925.43) U11.5@5774.78,3970.43
  Inner2 w23.62: v1(3920,3759.8) 5499.15,3759.8 5664.78,3925.43 v1(5774.78,3925.43)
AGND: C24.1 USB1.0 USB2.0 USB3.0 USBC1.0 USBC1.1 USBC1.2 USBC1.3 | length 2977.7
  Top Layer w10: USB2.0@6534.55,4960.4 USB2.0@6536.01,4958.94
  Top Layer w31.5: USB3.0@6539.55,3694.2 6565.6,3694.2 6667.84,3591.96 USBC1.1@6667.84,3500.08 USBC1.2@6832.4,3500.08 USBC1.3@6832.4,3159.52 ; USBC1.0@6667.84,3159.52 USBC1.3@6832.4,3159.52 ; C24.1@6831.46,3099.8 6831.46,3158.58 USBC1.3@6832.4,3159.52
  Top Layer w78.74: USB1.0@6534.55,5675.4 USB1.0@6534.55,5124.2 6534.55,5114.2 6536.01,5112.74 6536.01,4958.94 6536.02,4248.94 USB3.0@6539.55,4245.4 USB3.0@6539.55,3694.2
BOOT: BOOT.2 C62.2 R21.2 U2.94 | length 981.5
  Top Layer w10: C62.2@3915,4211.26 3967.62,4211.26 ; BOOT.2@3970,4268.78 3970,4213.64 3967.62,4211.26 ; v1(4015,4247.87) 4015,4226.84 R21.2@4000,4211.84 3999.42,4211.26 3967.62,4211.26 ; U2.94@4662.76,4266.69 4727.76,4266.69 v1(4732.76,4261.69)
  Bottom Layer w10: v1(4015,4247.87) 4028.82,4261.69 v1(4732.76,4261.69)
C_DN: D9.4 USBC1.A7 USBC1.B7 | length 365.8
  Top Layer w10: D9.4@6465.24,3197.4 6474.95,3197.4 6504.35,3226.8 6526.63,3226.8 6543.07,3243.25 6543.07,3294.8 6550.14,3301.88 6589.91,3301.88 6590.16,3302.12 6600.16,3302.12 6602,3300.27 USBC1.B7@6637.59,3300.27 6638.06,3299.8 6675,3299.8 6680,3304.8 6680,3334.8 6675.16,3339.64 USBC1.A7@6637.59,3339.64
C_DP: D9.6 USBC1.A6 USBC1.B6 | length 335.5
  Top Layer w10: D9.6@6465.24,3272.2 6474.95,3272.2 6504.35,3242.8 6520,3242.8 6527.07,3249.88 6527.07,3301.43 6543.51,3317.88 6583.29,3317.88 6583.53,3318.12 ; USBC1.A6@6637.59,3319.96 6602,3319.96 6600.16,3318.12 6583.53,3318.12 ; USBC1.B6@6637.59,3359.33 6594.53,3359.33 6583.53,3348.33 6583.53,3318.12
DAC1: H3.3 U2.28 | length 1976.6
  Top Layer w10: U2.28@5257.24,4187.95 5385,4187.95 5392.07,4195.03 5392.07,4491.88 5495,4594.8 5495,4754.8 5845,5104.8 5845,5279.8 6070,5504.8 6195,5504.8 6215,5524.8 H3.3@6215,5619.8
DAC2: H3.2 U2.29 | length 1855.7
  Top Layer w10: U2.29@5257.24,4207.63 5362.83,4207.63 5370,4214.8 5370,4504.8 5475,4609.8 5475,4769.8 5810,5104.8 5810,5294.8 6060,5544.8 6105,5544.8 6112.07,5551.88 6112.07,5616.88 H3.2@6115,5619.8
DEBUG_RX: H2.2 U2.47 | length 1844.4
  Top Layer w10: U2.47@5257.24,4561.97 5302.89,4561.97 v1(5314.34,4550.52)
  Bottom Layer w10: H2.2@5110,3134.8 5100,3144.8 5100,3234.8 5125,3259.8 5340,3259.8 5370,3289.8 5370,4474.8 5360,4484.8 5287.14,4484.8 5267.14,4504.8 5267.14,4537.66 5280,4550.52 v1(5314.34,4550.52)
DEBUG_TX: H2.3 U2.46 | length 1703.6
  Top Layer w10: U2.46@5257.24,4542.28 5290.06,4542.28 5304.82,4527.53 5333.08,4527.53 v1(5333.43,4527.18)
  Bottom Layer w10: H2.3@5210,3134.8 5210,3209.8 5225,3224.8 5380,3224.8 5400,3244.8 5400,4514.8 5390,4524.8 5335.8,4524.8 v1(5333.43,4527.18)
DUP_CTRL: U2.52 U5.1 U5.7 | length 1106.5
  Top Layer w10: U2.52@5176.54,4682.04 5176.54,4756.34 5200,4779.8 5320,4779.8 5565,5024.8 5565,5184.8 5719.18,5338.98 5719.18,5423.98 5739.53,5444.33 U5.1@5739.53,5485.02
DUP_RX: U2.54 U5.6 | length 1071.2
  Top Layer w10: U2.54@5137.17,4682.04 5137.17,4781.97 5195,4839.8 5300,4839.8 5505,5044.8 5505,5214.8 5660,5369.8 5660,5399.8 5675,5414.8 5690,5414.8 5700,5404.8 U5.6@5700,5379.74
DUP_SERVO: CN1.1 U5.2 U5.3 | length 129.6
  Top Layer w10: U5.3@5700.16,5485.02 5711,5485.02 ; CN1.1@5711.26,5594.8 5711.26,5485.28 5711,5485.02 ; U5.2@5719.84,5485.02 5711,5485.02
DUP_TX: U2.53 U5.5 | length 968.2
  Top Layer w10: U2.53@5156.85,4682.04 5156.85,4766.65 5200,4809.8 5310,4809.8 5535,5034.8 5535,5194.8 5680,5339.8 U5.5@5680,5369.11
